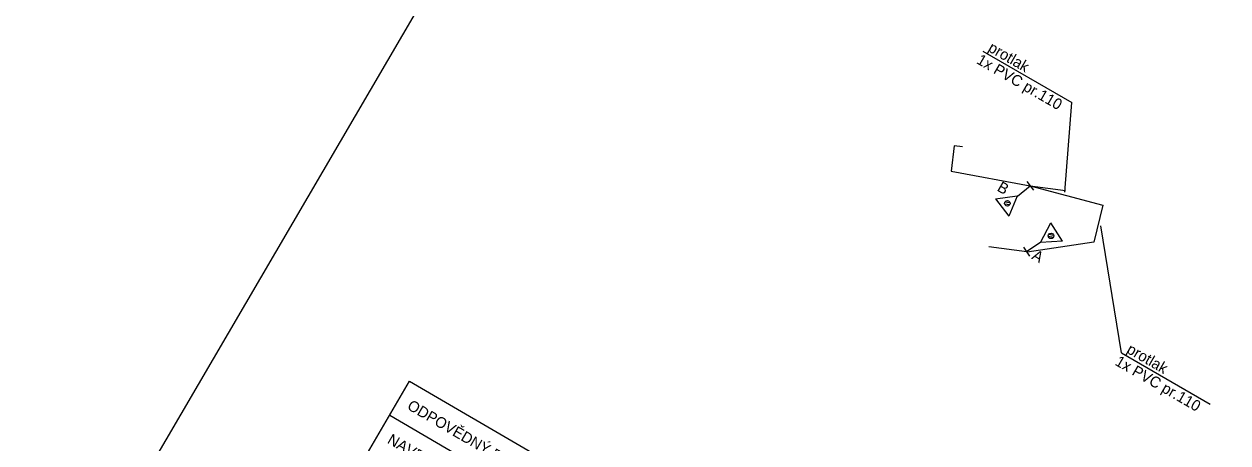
# Model space of a CAD drawing. Extents: x -805531 to -804081, y -1165633 to -1164726.
# Drawn here: x -804948.3 to -804728.3, y -1165157.7 to -1165081.2 of the extents above; entities that cross this region are included whole.
import ezdxf

# ---------------------------------------------------------------- set-up
doc = ezdxf.new("R2010")
doc.units = 0
for name, color, linetype in [('1_1000_Ramecek_rozpiska', 7, 'Continuous'), ('Implicitní', 7, 'Continuous'), ('Kolej_žkm_atd', 7, 'Continuous'), ('Nez po migraci', 7, 'Continuous'), ('Prvky_zab_zar', 7, 'Continuous'), ('Ramecky', 7, 'Continuous'), ('Vrstva 17', 7, 'Continuous')]:
    doc.layers.add(name, color=color, linetype=linetype)

msp = doc.modelspace()

# ---------------------------------------------------------------- linework, layer by layer
at = {"layer": '1_1000_Ramecek_rozpiska'}
msp.add_lwpolyline([(-804776.85, -1165103.59), (-804778.34, -1165103.41), (-804778.92, -1165108.04), (-804764.44, -1165110.74), (-804751.18, -1165114.27), (-804752.83, -1165121.07), (-804765.02, -1165122.88)], dxfattribs=at)
at = {"layer": 'Kolej_žkm_atd'}
for p, q in [((-804773.1, -1165086.13), (-804756.86, -1165095.51)), ((-804758.1, -1165111.89), (-804756.86, -1165095.51)), ((-804747.79, -1165141.26), (-804751.58, -1165118.06)), ((-804747.79, -1165141.26), (-804731.55, -1165150.64))]:
    msp.add_line(p, q, dxfattribs=at)
at = {"layer": 'Nez po migraci'}
for p, q in [((-804766.8, -1165112.61), (-804764.46, -1165110.75)), ((-804765.05, -1165109.97), (-804763.84, -1165111.51)), ((-804770.79, -1165113.13), (-804766.83, -1165112.57)), ((-804770.79, -1165113.13), (-804768.38, -1165116.31)), ((-804768.11, -1165113.84), (-804769.08, -1165113.75)), ((-804766.82, -1165112.61), (-804768.38, -1165116.31)), ((-804768.22, -1165114.22), (-804769.08, -1165114.11)), ((-804762.55, -1165121.09), (-804760.71, -1165117.52)), ((-804758.56, -1165120.89), (-804760.71, -1165117.52)), ((-804761.17, -1165119.97), (-804760.21, -1165120.13)), ((-804761.04, -1165119.6), (-804760.19, -1165119.77)), ((-804772.01, -1165121.85), (-804765.07, -1165122.76)), ((-804764.53, -1165123.58), (-804765.62, -1165121.95)), ((-804762.57, -1165121.08), (-804765.06, -1165122.76)), ((-804758.56, -1165120.89), (-804762.55, -1165121.13))]:
    msp.add_line(p, q, dxfattribs=at)
for centre in [(-804768.63, -1165113.95), (-804760.65, -1165119.89)]:
    msp.add_circle(centre, 0.5, dxfattribs=at)
at = {"layer": 'Prvky_zab_zar'}
msp.add_line((-804881.47, -1165152.65), (-804790.77, -1165205.62), dxfattribs=at)
msp.add_lwpolyline([(-804877.84, -1165146.44), (-804737.94, -1165228.13), (-804752.46, -1165253), (-804892.37, -1165171.31)], close=True, dxfattribs=at)
at = {"layer": 'Ramecky'}
msp.add_lwpolyline([(-804766.92, -1165307.51), (-804948.27, -1165201.62), (-804798.51, -1164945.14), (-804617.16, -1165051.03)], close=True, dxfattribs=at)
at = {"layer": 'Vrstva 17'}
msp.add_line((-804764.45, -1165110.74), (-804758, -1165111.59), dxfattribs=at)

# ---------------------------------------------------------------- texts
at = {"layer": 'Implicitní'}
for s, p in [('B', (-804770.66, -1165111.55)), ('A', (-804764.32, -1165124.01))]:
    msp.add_text(s, height=2, rotation=329.719, dxfattribs=at).set_placement(p)
at = {"layer": 'Kolej_žkm_atd'}
for s, p in [('protlak', (-804772.32, -1165086.04)), ('1x PVC pr.110', (-804774.42, -1165088.27)), ('protlak', (-804747.01, -1165141.17)), ('1x PVC pr.110', (-804749.12, -1165143.4))]:
    msp.add_text(s, height=2, rotation=330.0052, dxfattribs=at).set_placement(p)
at = {"layer": 'Prvky_zab_zar'}
for s, p in [('ODPOVĚDNÝ PROJEKTANT', (-804878.43, -1165151.46)), ('NAVRHL, VYPRACOVAL', (-804882.06, -1165157.67))]:
    msp.add_text(s, height=1.98, rotation=329.7524, dxfattribs=at).set_placement(p)

doc.saveas('drawing.dxf')
